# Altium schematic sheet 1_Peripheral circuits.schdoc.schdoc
size 309 x 223 mm; Symbol: Sheet-Symbol_A4; Device: Sheet-Symbol_A4; Company: 嘉立创EDA; Version: V1.0; Page Size: A4; @Project Name: Turbo; @Page Count: 2; @Update Date: 2024-03-01; @Create Date: 2024-02-19; @Schematic Name: Schematic; @Page No: 2; @Page Name: Peripheral circuits
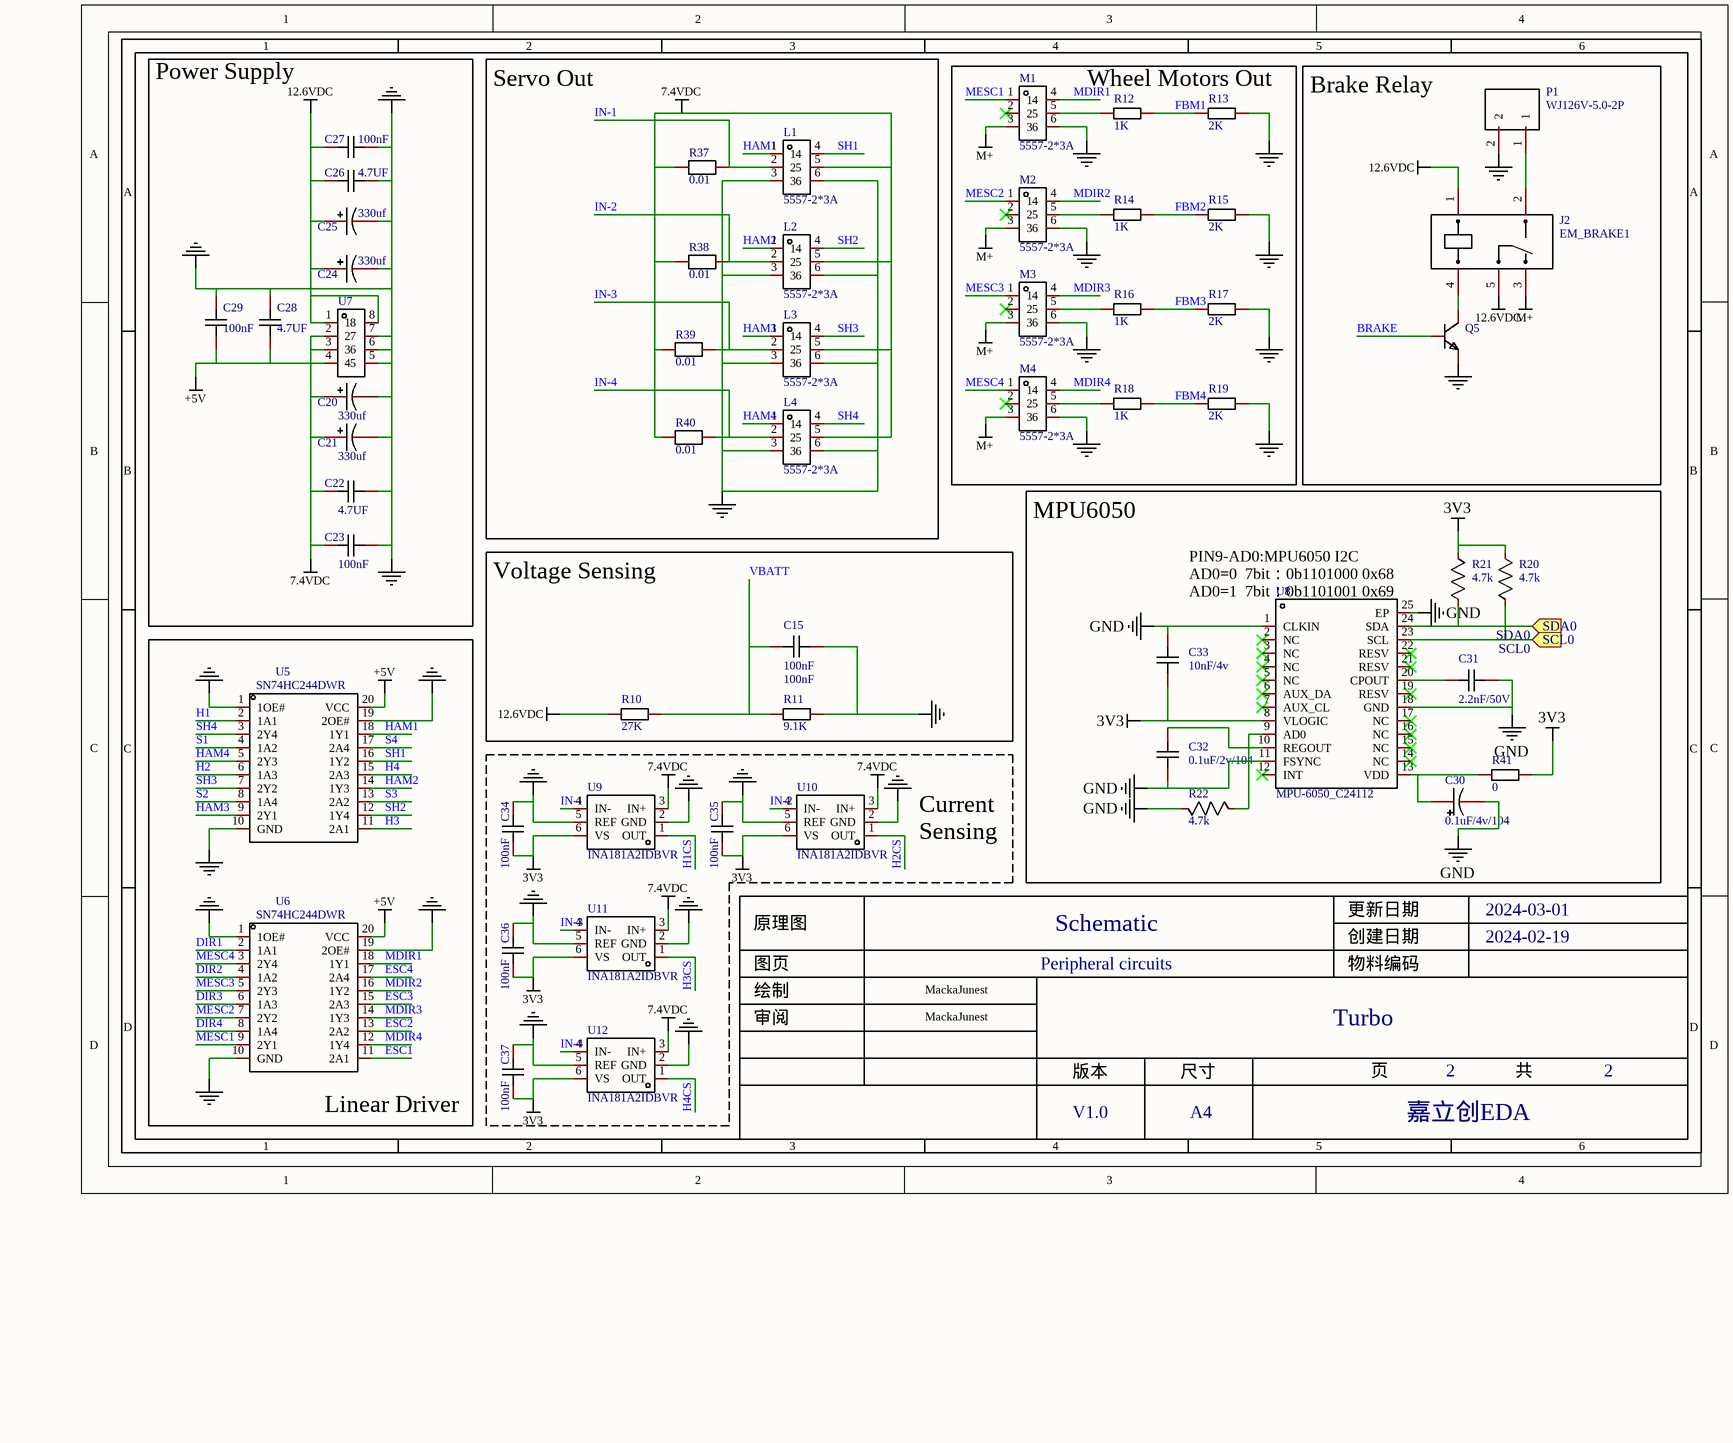
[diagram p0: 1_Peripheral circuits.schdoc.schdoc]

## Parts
C15  100nF  [C0603]
C20  330uf  [CAP-T-10*10.5]
C21  330uf  [CAP-T-10*10.5]
C22  4.7UF  [C0603]
C23  100nF  [C0603]
C24  330uf  [CAP-T-10*10.5]
C25  330uf  [CAP-T-10*10.5]
C26  4.7UF  [C0603]
C27  100nF  [C0603]
C28  4.7UF  [C0603]
C29  100nF  [C0603]
C30  0.1uF/4v/104  [CAP-SMD_L3.2-W1.6]
C31  2.2nF/50V  [C0603]
C32  0.1uF/2v/104  [C0603]
C33  10nF/4v  [C0603]
C34  100nF  [C0603]
C35  100nF  [C0603]
C36  100nF  [C0603]
C37  100nF  [C0603]
J2  EM_BRAKE1  [RELAY-TH_SRD-XXVDC-XL-C]
L1  5557-2*3A  [CONN-TH_5557-2X3A]
L2  5557-2*3A  [CONN-TH_5557-2X3A]
L3  5557-2*3A  [CONN-TH_5557-2X3A]
L4  5557-2*3A  [CONN-TH_5557-2X3A]
M1  5557-2*3A  [CONN-TH_5557-2X3A]
M2  5557-2*3A  [CONN-TH_5557-2X3A]
M3  5557-2*3A  [CONN-TH_5557-2X3A]
M4  5557-2*3A  [CONN-TH_5557-2X3A]
P1  WJ126V-5.0-2P  [CONN-TH_WJ126V-5.0-2P]
Q5  S8050_SOT_NPN  [S8050_SOT-23]  (value not drawn)
R10  27K  [R0603]
R11  9.1K  [R0603]
R12  1K  [R0603]
R13  2K  [R0603]
R14  1K  [R0603]
R15  2K  [R0603]
R16  1K  [R0603]
R17  2K  [R0603]
R18  1K  [R0603]
R19  2K  [R0603]
R20  4.7k  [R0603]
R21  4.7k  [R0603]
R22  4.7k  [R0603]
R37  0.01  [R2512]
R38  0.01  [R2512]
R39  0.01  [R2512]
R40  0.01  [R2512]
R41  0  [R0603]
U5  SN74HC244DWR  [SOIC-20_L13.0-W7.6-P1.27-LS10.6-BL]
U6  SN74HC244DWR  [SOIC-20_L13.0-W7.6-P1.27-LS10.6-BL]
U7  5557-2*4P直针座-黑色8芯  [CONN-TH_5557-2-4P]  (value not drawn)
U8  MPU-6050_C24112  [QFN-24_L4.0-W4.0-P0.50-BL-EP2.6]
U9  INA181A2IDBVR  [SOT-23-6_L2.9-W1.6-P0.95-LS2.8-BL]
U10  INA181A2IDBVR  [SOT-23-6_L2.9-W1.6-P0.95-LS2.8-BL]
U11  INA181A2IDBVR  [SOT-23-6_L2.9-W1.6-P0.95-LS2.8-BL]
U12  INA181A2IDBVR  [SOT-23-6_L2.9-W1.6-P0.95-LS2.8-BL]

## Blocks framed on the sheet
Power Supply: C20-C29 U7
Servo Out: L1-L4 R37-R40
Wheel Motors Out: M1-M4 R12-R19
Brake Relay: J2 P1 Q5
MPU6050: C30-C33 R20-R22 R41 U8
Voltage Sensing: C15 R10 R11
Linear Driver: U5 U6

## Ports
SCL0 (in), SDA0 (in)

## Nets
3V3: C33.1 C34.1 C35.1 C36.1 C37.1 R20.2 R21.2 R41.2 U8.8(VLOGIC) U9.6(VS) U10.6(VS) U11.6(VS) U12.6(VS)
7.4VDC: C20.1 C21.1 C22.1 C23.1 L1.5 L2.5 L3.5 L4.5 R37.2 R38.2 R39.2 R40.2 U7.2 U7.3 U9.3(IN+) U10.3(IN+) U11.3(IN+) U12.3(IN+)
12.6VDC: C24.1 C25.1 C26.1 C27.1 J2.1 J2.5 R10.1 U7.1 U7.8
+5V: C28.1 C29.1 U5.20(VCC) U6.20(VCC) U7.4
GND: C30.2 C31.1 C32.1 C33.2 R22.1 U8.1(CLKIN) U8.11(FSYNC) U8.18(GND) U8.25(EP)
M+: J2.3 M1.3 M2.3 M3.3 M4.3
NetC15_2: C15.2 C20.2 C21.2 C22.2 C23.2 C24.2 C25.2 C26.2 C27.2 C28.2 C29.2 C34.2 C35.2 C36.2 C37.2 L1.3 L1.6 L2.3 L2.6 L3.3 L3.6 L4.3 L4.6 M1.6 M2.6 M3.6 M4.6 P1.2 Q5.2 R11.2 R13.2 R15.2 R17.2 R19.2 U5.1(1OE#) U5.10(GND) U5.19(2OE#) U6.1(1OE#) U6.10(GND) U6.19(2OE#) U7.5 U7.6 U7.7 U9.2(GND) U9.5(REF) U10.2(GND) U10.5(REF) U11.2(GND) U11.5(REF) U12.2(GND) U12.5(REF)
BRAKE: Q5.1
DIR1: U6.2(1A1)
DIR2: U6.4(1A2)
DIR3: U6.6(1A3)
DIR4: U6.8(1A4)
ESC1: U6.11(2A1)
ESC2: U6.13(2A2)
ESC3: U6.15(2A3)
ESC4: U6.17(2A4)
FBM1: R12.2 R13.1
FBM2: R14.2 R15.1
FBM3: R16.2 R17.1
FBM4: R18.2 R19.1
H1: U5.2(1A1)
H1CS: U9.1(OUT)
H2: U5.6(1A3)
H2CS: U10.1(OUT)
H3: U5.11(2A1)
H3CS: U11.1(OUT)
H4: U5.15(2A3)
H4CS: U12.1(OUT)
HAM1: L1.1 U5.18(1Y1)
HAM2: L2.1 U5.14(1Y3)
HAM3: L3.1 U5.9(2Y1)
HAM4: L4.1 U5.5(2Y3)
IN-1: L1.2 R37.1 U9.4(IN-)
IN-2: L2.2 R38.1 U10.4(IN-)
IN-3: L3.2 R39.1 U11.4(IN-)
IN-4: L4.2 R40.1 U12.4(IN-)
MDIR1: M1.4 U6.18(1Y1)
MDIR2: M2.4 U6.16(1Y2)
MDIR3: M3.4 U6.14(1Y3)
MDIR4: M4.4 U6.12(1Y4)
MESC1: M1.1 U6.9(2Y1)
MESC2: M2.1 U6.7(2Y2)
MESC3: M3.1 U6.5(2Y3)
MESC4: M4.1 U6.3(2Y4)
S1: U5.4(1A2)
S2: U5.8(1A4)
S3: U5.13(2A2)
S4: U5.17(2A4)
SCL0: R20.1 U8.23(SCL) ; port SCL0
SDA0: R21.1 U8.24(SDA) ; port SDA0
SH1: L1.4 U5.16(1Y2)
SH2: L2.4 U5.12(1Y4)
SH3: L3.4 U5.7(2Y2)
SH4: L4.4 U5.3(2Y4)
VBATT: C15.1 R10.2 R11.1
NetC30_1: C30.1 R41.1 U8.13(VDD)
NetC31_2: C31.2 U8.20(CPOUT)
NetC32_2: C32.2 U8.10(REGOUT)
NetJ2_2: J2.2 P1.1
NetJ2_4: J2.4 Q5.3
NetM1_5: M1.5 R12.1
NetM2_5: M2.5 R14.1
NetM3_5: M3.5 R16.1
NetM4_5: M4.5 R18.1
NetR22_2: R22.2 U8.9(AD0)

Not connected (* = marked no-connect by the designer): M1 2*; M2 2*; M3 2*; M4 2*; U8 2(NC)* 3(NC)* 4(NC)* 5(NC)* 6(AUX_DA)* 7(AUX_CL)* 12(INT)* 14(NC)* 15(NC)* 16(NC)* 17(NC)* 19(RESV)* 21(RESV)* 22(RESV)*

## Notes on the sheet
- (near U8) PIN9-AD0:MPU6050 I2C
  AD0=0  7bit：0b1101000 0x68
  AD0=1  7bit：0b1101001 0x69
- Current
  Sensing
- MackaJunest

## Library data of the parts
C15 C22 C23 C26-C29 C34-C37 = CAP_0603: Symbol: CapAcitance; Convert to PCB: yes
C20 C21 C24 C25 = 330uf: 3DModel: CAP-SMD_BD10.5-L10.8-W10.8-LS12.2; Add into BOM: yes
C30 = 0.1uF/4v/104: Manufacturer: AVX; Manufacturer Part: TPSA106K016R1000; Convert to PCB: yes
C31 = 2.2nF/50V: Convert to PCB: yes; Origin Footprint: C0402
C32 = 0.1uF/2v/104: Convert to PCB: yes; Origin Footprint: C0402
C33 = 10nF/4v: Convert to PCB: yes; Origin Footprint: C0402
J2 = SRD-12VDC-SL-C: Manufacturer: 松乐; Add into BOM: yes; Coil Voltage: 12V; Contact Form: 一组转换:1C(单刀双掷-转换); Pin Number: 5; Maximum Switching Voltage: 250V@AC; Coil Rated Power: 360mW; Maximum Switching Current: 15A; Coil Type: 无极性-单线圈; Coil Resistance: 400Ω; Contact Resistance: 100mΩ; Operate Time: 10ms; Description: 线圈电压:12V;触点形式:一组转换:1C(单刀双掷-转换);触点容量(电阻负载):-;最大切换电压:250V@AC;最大切换电流:15A;
L1-L4 M1-M4 = 5557-2*3A: Manufacturer: FG(富港); Add into BOM: yes
P1 = WJ126V-5.0-2P: Manufacturer: KANGNEX(康奈克斯电气); Add into BOM: yes; Structure: 1x2P; Pitch: 5mm; Current Rating (Max): 18A; Voltage Rating (Max): 250V; Wire Gauge - AWG: 14~26; Wire Gauge - mm2: 2.5; Number of PINs Per Row: 2; Description: 结构:1x2P;间距:5mm;颜色:绿色;安装方式:直插;额定电流:18A;额定电压:250V;排数:1;线规 - AWG:14~26;线规 - 平方毫米:2.5;每排PIN数:2;工作温度范围:-40℃~+105℃;
Q5 = S8050_SOT_NPN: Symbol: NPN; Convert to PCB: yes
R10-R19 R41 = Res_0603: Symbol: 电阻; Convert to PCB: yes
R20-R22 = 4.7k: Convert to PCB: yes; Origin Footprint: C0402
R37-R40 = 0.01: 3DModel: R2512_L6.3-W3.2-H0.6; Add into BOM: yes
U5 U6 = SN74HC244DWR: Manufacturer: TI; Manufacturer Part: SN74AHC244DWR; 3DModel: SOIC-20_L12.8-W7.5-H2.7-LS10.3-P1.27; Add into BOM: yes
U7 = 5557-2*4P直针座-黑色8芯: Add into BOM: yes
U8 = MPU-6050_C24112: Manufacturer: InvenSense; Convert to PCB: yes
U9-U12 = INA181A2IDBVR: Manufacturer: TI(德州仪器); Add into BOM: yes; Number of Channels: 单路; Supply Current: 260uA; Description: 放大器数:单路;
